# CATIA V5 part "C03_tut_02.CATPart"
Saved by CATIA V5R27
Part number: Part1
Bounding box of the stored display mesh (mm): x 0 to 0, y -39.999 to 150, z -39.996 to 39.994
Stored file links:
  E:\_Deepak\2017_Deepak\CATIA\Resources\Tutorial Files\Tutorials\c03_catia_v5_6r2016_tut\C03_tut_02.CATPart
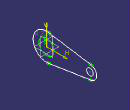
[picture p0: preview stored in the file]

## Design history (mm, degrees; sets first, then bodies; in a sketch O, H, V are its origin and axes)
Body1 (main body)
  Sketch1 on yz-plane, origin (0, 0, 0), H (0, 1, 0), V (0, 0, 1)
    arc A1 centre (0, 0) radius 40 from (6.1538, 39.5238) to (6.1538, -39.5238) ccw
    arc A2 centre (130, 0) radius 20 from (133.0769, -19.7619) to (133.0769, 19.7619) ccw
    line L1 (6.1538, 39.5238) -> (133.0769, 19.7619)
    line L2 (133.0769, -19.7619) -> (6.1538, -39.5238)
    circle A3 centre (0, 0) radius 22.5
    circle A4 centre (130, 0) radius 10
    radius A3 = 22.5
    tangency: L1 A1, L1 A2, L2 A2, L2 A1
